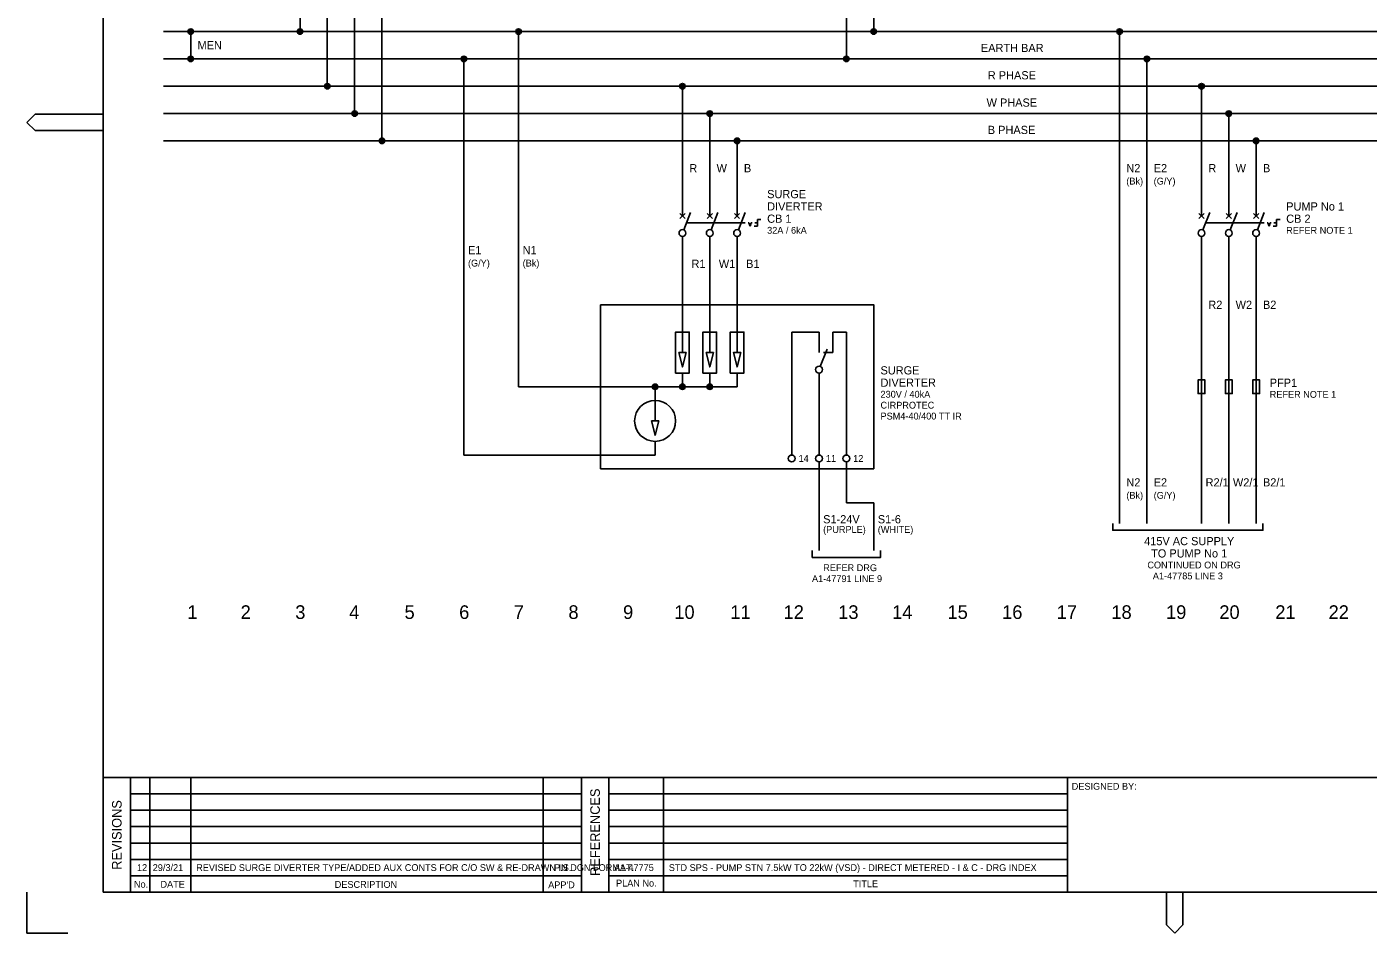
# Model space of a CAD drawing. Extents: x 0 to 841, y 0 to 594.
# Drawn here: x 0 to 491, y 0 to 331.7 of the extents above; entities that cross this region are included whole.
import ezdxf

# ---------------------------------------------------------------- set-up
doc = ezdxf.new("R2010")
doc.units = 0
for name, color, linetype in [('A1BORDER', 7, 'Continuous'), ('BASE', 7, 'Continuous'), ('Level 1', 7, 'Continuous'), ('Level 10', 7, 'Continuous')]:
    doc.layers.add(name, color=color, linetype=linetype)

msp = doc.modelspace()

# ---------------------------------------------------------------- linework, layer by layer
at = {"layer": 'A1BORDER'}
for p, q in [((28, 581), (28, 15)), ((3, 299.76), (0, 296.76)), ((28, 299.76), (3, 299.76)), ((3, 293.76), (0, 296.76)), ((28, 293.76), (3, 293.76)), ((28, 57), (829, 57)), ((38, 15), (38, 57)), ((45, 15), (45, 57)), ((60, 15), (60, 57)), ((189, 15), (189, 57)), ((203, 15), (203, 57)), ((213, 15), (213, 57)), ((233, 15), (233, 57)), ((381, 15), (381, 57)), ((203, 51), (38, 51)), ((213, 51), (381, 51)), ((203, 45), (38, 45)), ((213, 45), (381, 45)), ((203, 39), (38, 39)), ((213, 39), (381, 39)), ((203, 33), (38, 33)), ((213, 33), (381, 33)), ((38, 27), (203, 27)), ((213, 27), (381, 27)), ((203, 21), (38, 21)), ((213, 21), (381, 21)), ((0, 0), (0, 15)), ((829, 15), (28, 15)), ((417.19, 15), (417.19, 3)), ((423.19, 15), (423.19, 3)), ((417.19, 3), (420.19, 0)), ((423.19, 3), (420.19, 0)), ((0, 0), (15, 0))]:
    msp.add_line(p, q, dxfattribs=at)
at = {"layer": 'Level 1'}
for p, q in [((300, 320), (300, 545)), ((100, 330), (100, 445)), ((110, 375), (110, 310)), ((120, 375), (120, 300)), ((130, 375), (130, 290)), ((310, 330), (310, 375)), ((50, 330), (800, 330)), ((60, 330), (60, 320)), ((180, 330), (180, 200)), ((400, 330), (400, 150)), ((50, 320), (800, 320)), ((160, 320), (160, 175)), ((410, 320), (410, 150)), ((800, 310), (50, 310)), ((240, 310), (240, 265)), ((430, 310), (430, 265)), ((50, 300), (800, 300)), ((250, 300), (250, 265)), ((440, 300), (440, 265)), ((50, 290), (800, 290)), ((260, 290), (260, 265)), ((450, 290), (450, 265)), ((239.06, 263.44), (240.94, 261.56)), ((240.94, 263.44), (239.06, 261.56)), ((240, 262.5), (240, 265)), ((240.46, 257.41), (243, 263.75)), ((249.06, 263.44), (250.94, 261.56)), ((250.94, 263.44), (249.06, 261.56)), ((250, 262.5), (250, 265)), ((250.46, 257.41), (253, 263.75)), ((259.06, 263.44), (260.94, 261.56)), ((260.94, 263.44), (259.06, 261.56)), ((260, 262.5), (260, 265)), ((260.46, 257.41), (263, 263.75)), ((429.06, 263.44), (430.94, 261.56)), ((430.94, 263.44), (429.06, 261.56)), ((430, 262.5), (430, 265)), ((430.46, 257.41), (433, 263.75)), ((439.06, 263.44), (440.94, 261.56)), ((440.94, 263.44), (439.06, 261.56)), ((440, 262.5), (440, 265)), ((440.46, 257.41), (443, 263.75)), ((449.06, 263.44), (450.94, 261.56)), ((450.94, 263.44), (449.06, 261.56)), ((450, 262.5), (450, 265)), ((450.46, 257.41), (453, 263.75)), ((241.5, 260), (261.5, 260)), ((431.5, 260), (451.5, 260)), ((240, 255), (240, 220)), ((250, 255), (250, 220)), ((260, 255), (260, 220)), ((430, 255), (430, 150)), ((440, 255), (440, 150)), ((450, 255), (450, 150)), ((240, 237.5), (240, 237.5)), ((260, 237.5), (260, 237.5)), ((240, 212.5), (240, 220)), ((250, 212.5), (250, 220)), ((260, 212.5), (260, 220)), ((280, 220), (280, 175)), ((290, 220), (280, 220)), ((290, 220), (290, 215)), ((300, 220), (295, 220)), ((295, 220), (295, 215)), ((300, 175), (300, 220)), ((240, 205), (240, 200)), ((250, 205), (250, 200)), ((260, 205), (260, 200)), ((290, 205), (290, 175)), ((180, 200), (260, 200)), ((230, 200), (230, 195)), ((230, 187.5), (230, 195)), ((230, 180), (230, 175)), ((160, 175), (230, 175)), ((290, 172.5), (290, 140)), ((300, 172.5), (300, 157.5)), ((310, 157.5), (300, 157.5)), ((310, 157.5), (310, 140))]:
    msp.add_line(p, q, dxfattribs=at)
for points in [[(210, 230), (310, 230), (310, 170), (210, 170)], [(241.32, 212.5), (240, 207.26), (238.68, 212.5)], [(251.32, 212.5), (250, 207.26), (248.68, 212.5)], [(261.32, 212.5), (260, 207.26), (258.68, 212.5)], [(231.32, 187.5), (230, 182.26), (228.68, 187.5)]]:
    msp.add_lwpolyline(points, close=True, dxfattribs=at)
for points in [[(397.5, 150), (397.5, 147.5), (452.5, 147.5), (452.5, 150)], [(287.5, 140), (287.5, 137.5), (312.5, 137.5), (312.5, 140)]]:
    msp.add_lwpolyline(points, dxfattribs=at)
for centre, radius in [((240, 256.25), 1.25), ((250, 256.25), 1.25), ((260, 256.25), 1.25), ((430, 256.25), 1.25), ((440, 256.25), 1.25), ((450, 256.25), 1.25), ((230, 187.5), 7.5)]:
    msp.add_circle(centre, radius, dxfattribs=at)
at = {"layer": 'Level 10'}
for p, q in [((59.01, 330.1), (60.99, 330.1)), ((59.02, 329.8), (60.98, 329.8)), ((59.08, 330.4), (60.92, 330.4)), ((59.13, 329.5), (60.87, 329.5)), ((59.29, 330.7), (60.71, 330.7)), ((59.4, 329.2), (60.6, 329.2)), ((60, 331), (60, 331)), ((99.01, 330.1), (100.99, 330.1)), ((99.02, 329.8), (100.98, 329.8)), ((99.08, 330.4), (100.92, 330.4)), ((99.13, 329.5), (100.87, 329.5)), ((99.29, 330.7), (100.71, 330.7)), ((99.4, 329.2), (100.6, 329.2)), ((100, 331), (100, 331)), ((179.01, 330.1), (180.99, 330.1)), ((179.02, 329.8), (180.98, 329.8)), ((179.08, 330.4), (180.92, 330.4)), ((179.13, 329.5), (180.87, 329.5)), ((179.29, 330.7), (180.71, 330.7)), ((179.4, 329.2), (180.6, 329.2)), ((180, 331), (180, 331)), ((309.01, 330.1), (310.99, 330.1)), ((309.02, 329.8), (310.98, 329.8)), ((309.08, 330.4), (310.92, 330.4)), ((309.13, 329.5), (310.87, 329.5)), ((309.29, 330.7), (310.71, 330.7)), ((309.4, 329.2), (310.6, 329.2)), ((310, 331), (310, 331)), ((399.01, 330.1), (400.99, 330.1)), ((399.02, 329.8), (400.98, 329.8)), ((399.08, 330.4), (400.92, 330.4)), ((399.13, 329.5), (400.87, 329.5)), ((399.29, 330.7), (400.71, 330.7)), ((399.4, 329.2), (400.6, 329.2)), ((400, 331), (400, 331)), ((59.01, 320.1), (60.99, 320.1)), ((59.02, 319.8), (60.98, 319.8)), ((59.08, 320.4), (60.92, 320.4)), ((59.13, 319.5), (60.87, 319.5)), ((59.29, 320.7), (60.71, 320.7)), ((59.4, 319.2), (60.6, 319.2)), ((60, 321), (60, 321)), ((159.01, 320.1), (160.99, 320.1)), ((159.02, 319.8), (160.98, 319.8)), ((159.08, 320.4), (160.92, 320.4)), ((159.13, 319.5), (160.87, 319.5)), ((159.29, 320.7), (160.71, 320.7)), ((159.4, 319.2), (160.6, 319.2)), ((160, 321), (160, 321)), ((299.01, 320.1), (300.99, 320.1)), ((299.02, 319.8), (300.98, 319.8)), ((299.08, 320.4), (300.92, 320.4)), ((299.13, 319.5), (300.87, 319.5)), ((299.29, 320.7), (300.71, 320.7)), ((299.4, 319.2), (300.6, 319.2)), ((300, 321), (300, 321)), ((409.01, 320.1), (410.99, 320.1)), ((409.02, 319.8), (410.98, 319.8)), ((409.08, 320.4), (410.92, 320.4)), ((409.13, 319.5), (410.87, 319.5)), ((409.29, 320.7), (410.71, 320.7)), ((409.4, 319.2), (410.6, 319.2)), ((410, 321), (410, 321)), ((109.01, 310.1), (110.99, 310.1)), ((109.02, 309.8), (110.98, 309.8)), ((109.08, 310.4), (110.92, 310.4)), ((109.13, 309.5), (110.87, 309.5)), ((109.29, 310.7), (110.71, 310.7)), ((110, 311), (110, 311)), ((239.01, 310.1), (240.99, 310.1)), ((239.02, 309.8), (240.98, 309.8)), ((239.08, 310.4), (240.92, 310.4)), ((239.13, 309.5), (240.87, 309.5)), ((239.29, 310.7), (240.71, 310.7)), ((240, 311), (240, 311)), ((429.01, 310.1), (430.99, 310.1)), ((429.02, 309.8), (430.98, 309.8)), ((429.08, 310.4), (430.92, 310.4)), ((429.13, 309.5), (430.87, 309.5)), ((429.29, 310.7), (430.71, 310.7)), ((430, 311), (430, 311)), ((109.4, 309.2), (110.6, 309.2)), ((239.4, 309.2), (240.6, 309.2)), ((429.4, 309.2), (430.6, 309.2)), ((119.01, 300.1), (120.99, 300.1)), ((119.02, 299.8), (120.98, 299.8)), ((119.08, 300.4), (120.92, 300.4)), ((119.29, 300.7), (120.71, 300.7)), ((120, 301), (120, 301)), ((249.01, 300.1), (250.99, 300.1)), ((249.02, 299.8), (250.98, 299.8)), ((249.08, 300.4), (250.92, 300.4)), ((249.29, 300.7), (250.71, 300.7)), ((250, 301), (250, 301)), ((439.01, 300.1), (440.99, 300.1)), ((439.02, 299.8), (440.98, 299.8)), ((439.08, 300.4), (440.92, 300.4)), ((439.29, 300.7), (440.71, 300.7)), ((440, 301), (440, 301)), ((119.13, 299.5), (120.87, 299.5)), ((119.4, 299.2), (120.6, 299.2)), ((249.13, 299.5), (250.87, 299.5)), ((249.4, 299.2), (250.6, 299.2)), ((439.13, 299.5), (440.87, 299.5)), ((439.4, 299.2), (440.6, 299.2)), ((129.01, 290.1), (130.99, 290.1)), ((129.02, 289.8), (130.98, 289.8)), ((129.08, 290.4), (130.92, 290.4)), ((129.29, 290.7), (130.71, 290.7)), ((130, 291), (130, 291)), ((259.01, 290.1), (260.99, 290.1)), ((259.02, 289.8), (260.98, 289.8)), ((259.08, 290.4), (260.92, 290.4)), ((259.29, 290.7), (260.71, 290.7)), ((260, 291), (260, 291)), ((449.01, 290.1), (450.99, 290.1)), ((449.02, 289.8), (450.98, 289.8)), ((449.08, 290.4), (450.92, 290.4)), ((449.29, 290.7), (450.71, 290.7)), ((450, 291), (450, 291)), ((129.13, 289.5), (130.87, 289.5)), ((129.4, 289.2), (130.6, 289.2)), ((259.13, 289.5), (260.87, 289.5)), ((259.4, 289.2), (260.6, 289.2)), ((449.13, 289.5), (450.87, 289.5)), ((449.4, 289.2), (450.6, 289.2)), ((267.5, 258.75), (267.5, 261.25)), ((267.5, 261.25), (268.75, 261.25)), ((457.5, 258.75), (457.5, 261.25)), ((457.5, 261.25), (458.75, 261.25)), ((261.5, 260), (263, 260)), ((264, 260), (264.33, 260)), ((264.75, 258.75), (264.33, 260)), ((264.75, 258.75), (265.17, 260)), ((265.5, 260), (265.17, 260)), ((266.25, 258.75), (267.5, 258.75)), ((266.5, 260), (267.5, 260)), ((451.5, 260), (453, 260)), ((454, 260), (454.33, 260)), ((454.75, 258.75), (454.33, 260)), ((454.75, 258.75), (455.17, 260)), ((455.5, 260), (455.17, 260)), ((456.25, 258.75), (457.5, 258.75)), ((456.5, 260), (457.5, 260)), ((290, 212.5), (290, 215)), ((290.46, 207.41), (293, 213.75)), ((291.63, 212.5), (295, 212.5)), ((295, 212.5), (295, 215)), ((229.01, 200.1), (230.99, 200.1)), ((229.02, 199.8), (230.98, 199.8)), ((229.08, 200.4), (230.92, 200.4)), ((229.13, 199.5), (230.87, 199.5)), ((229.29, 200.7), (230.71, 200.7)), ((229.4, 199.2), (230.6, 199.2)), ((230, 201), (230, 201)), ((239.01, 200.1), (240.99, 200.1)), ((239.02, 199.8), (240.98, 199.8)), ((239.08, 200.4), (240.92, 200.4)), ((239.13, 199.5), (240.87, 199.5)), ((239.29, 200.7), (240.71, 200.7)), ((239.4, 199.2), (240.6, 199.2)), ((240, 201), (240, 201)), ((249.01, 200.1), (250.99, 200.1)), ((249.02, 199.8), (250.98, 199.8)), ((249.08, 200.4), (250.92, 200.4)), ((249.13, 199.5), (250.87, 199.5)), ((249.29, 200.7), (250.71, 200.7)), ((249.4, 199.2), (250.6, 199.2)), ((250, 201), (250, 201))]:
    msp.add_line(p, q, dxfattribs=at)
for points in [[(240, 220), (237.5, 220), (237.5, 205), (242.5, 205), (242.5, 220), (240, 220)], [(250, 220), (247.5, 220), (247.5, 205), (252.5, 205), (252.5, 220), (250, 220)], [(260, 220), (257.5, 220), (257.5, 205), (262.5, 205), (262.5, 220), (260, 220)], [(430, 197.5), (431.25, 197.5), (431.25, 202.5), (428.75, 202.5), (428.75, 197.5), (430, 197.5)], [(440, 197.5), (441.25, 197.5), (441.25, 202.5), (438.75, 202.5), (438.75, 197.5), (440, 197.5)], [(450, 197.5), (451.25, 197.5), (451.25, 202.5), (448.75, 202.5), (448.75, 197.5), (450, 197.5)]]:
    msp.add_lwpolyline(points, dxfattribs=at)
for centre, radius in [((60, 330), 1), ((100, 330), 1), ((180, 330), 1), ((310, 330), 1), ((400, 330), 1), ((60, 320), 1), ((160, 320), 1), ((300, 320), 1), ((410, 320), 1), ((110, 310), 1), ((240, 310), 1), ((430, 310), 1), ((120, 300), 1), ((250, 300), 1), ((440, 300), 1), ((130, 290), 1), ((260, 290), 1), ((450, 290), 1), ((290, 206.25), 1.25), ((230, 200), 1), ((240, 200), 1), ((250, 200), 1), ((280, 173.75), 1.25), ((290, 173.75), 1.25), ((300, 173.75), 1.25)]:
    msp.add_circle(centre, radius, dxfattribs=at)

# ---------------------------------------------------------------- texts
at = {"layer": 'A1BORDER'}
for s, p in [('DESIGNED BY:', (382.5, 52.5)), ('No.', (39.21, 16.65)), ('DATE', (48.92, 16.65)), ('DESCRIPTION', (112.71, 16.57)), ("APP'D", (190.85, 16.44)), ('PLAN No.', (215.69, 17.06)), ('TITLE', (302.5, 16.81))]:
    msp.add_text(s, height=2.5, dxfattribs=at).set_placement(p)
for s, p in [('REFERENCES', (209.76, 20.96)), ('REVISIONS', (34.68, 23.2))]:
    msp.add_text(s, height=3.5, rotation=90, dxfattribs=at).set_placement(p)
at = {"layer": 'BASE'}
for s, p in [('14', (282.5, 172.5)), ('11', (292.5, 172.5)), ('12', (302.5, 172.5))]:
    msp.add_text(s, height=2.5, dxfattribs=at).set_placement(p)
at = {"layer": 'Level 1'}
for s, height, p in [('MEN', 3, (62.5, 323.5)), ('EARTH BAR', 3, (349.24, 322.5)), ('R PHASE', 3, (351.78, 312.5)), ('W PHASE', 3, (351.33, 302.5)), ('B PHASE', 3, (351.78, 292.5)), ('R', 3, (242.5, 278.5)), ('W', 3, (252.5, 278.5)), ('B', 3, (262.5, 278.5)), ('N2', 3, (402.5, 278.5)), ('E2', 3, (412.5, 278.5)), ('R', 3, (432.5, 278.5)), ('W', 3, (442.5, 278.5)), ('B', 3, (452.5, 278.5)), ('(Bk)', 2.5, (402.5, 274)), ('(G/Y)', 2.5, (412.5, 274)), ('SURGE', 3, (271, 269.01)), ('DIVERTER', 3, (271, 264.51)), ('PUMP No 1', 3, (461, 264.5)), ('CB 1', 3, (271, 260.01)), ('CB 2', 3, (461, 260)), ('32A / 6kA', 2.5, (271, 256)), ('REFER NOTE 1', 2.5, (461, 256)), ('E1', 3, (161.5, 248.5)), ('N1', 3, (181.5, 248.5)), ('(G/Y)', 2.5, (161.5, 244)), ('(Bk)', 2.5, (181.5, 244)), ('R1', 3, (243.31, 243.5)), ('W1', 3, (253.31, 243.5)), ('B1', 3, (263.31, 243.5)), ('R2', 3, (432.5, 228.5)), ('W2', 3, (442.5, 228.5)), ('B2', 3, (452.5, 228.5)), ('SURGE', 3, (312.5, 204.5)), ('DIVERTER', 3, (312.5, 200)), ('PFP1', 3, (454.98, 199.96)), ('230V / 40kA', 2.5, (312.5, 196)), ('REFER NOTE 1', 2.5, (454.98, 195.96)), ('CIRPROTEC', 2.5, (312.5, 192)), ('PSM4-40/400 TT IR', 2.5, (312.5, 188)), ('N2', 3, (402.5, 163.5)), ('E2', 3, (412.5, 163.5)), ('R2/1', 3, (431.5, 163.5)), ('W2/1', 3, (441.5, 163.5)), ('B2/1', 3, (452.5, 163.5)), ('(Bk)', 2.5, (402.5, 159)), ('(G/Y)', 2.5, (412.5, 159)), ('S1-24V', 3, (291.5, 150)), ('S1-6', 3, (311.5, 150)), ('(PURPLE)', 2.5, (291.5, 146.5)), ('(WHITE)', 2.5, (311.5, 146.5)), ('415V AC SUPPLY', 3, (409.01, 142)), ('TO PUMP No 1', 3, (411.55, 137.5)), ('REFER DRG', 2.5, (291.53, 132.5)), ('CONTINUED ON DRG', 2.5, (410.18, 133.5)), ('A1-47791 LINE 9', 2.5, (287.42, 128.5)), ('A1-47785 LINE 3', 2.5, (412.18, 129.5)), ('1', 5, (58.76, 115)), ('2', 5, (78.26, 115)), ('3', 5, (98.26, 115)), ('4', 5, (118.01, 115)), ('5', 5, (138.26, 115)), ('6', 5, (158.26, 115)), ('7', 5, (178.26, 115)), ('8', 5, (198.26, 115)), ('9', 5, (218.26, 115)), ('10', 5, (237.01, 115)), ('11', 5, (257.51, 115)), ('12', 5, (277.01, 115)), ('13', 5, (297.01, 115)), ('14', 5, (316.76, 115)), ('15', 5, (337.01, 115)), ('16', 5, (357.01, 115)), ('17', 5, (377.01, 115)), ('18', 5, (397.01, 115)), ('19', 5, (417.01, 115)), ('20', 5, (436.52, 115)), ('21', 5, (457.01, 115)), ('22', 5, (476.52, 115)), ('12', 2.5, (40.32, 22.75)), ('29/3/21', 2.5, (46.09, 22.75)), ('REVISED SURGE DIVERTER TYPE/ADDED AUX CONTS FOR C/O SW & RE-DRAWN IN DGN FORMAT.', 2.5, (62, 22.75)), ('P.S.', 2.5, (193.02, 22.75)), ('A1-47775', 2.5, (215, 22.75)), ('STD SPS - PUMP STN 7.5kW TO 22kW (VSD) - DIRECT METERED - I & C - DRG INDEX', 2.5, (235, 22.75))]:
    msp.add_text(s, height=height, dxfattribs=at).set_placement(p)

doc.saveas('drawing.dxf')
